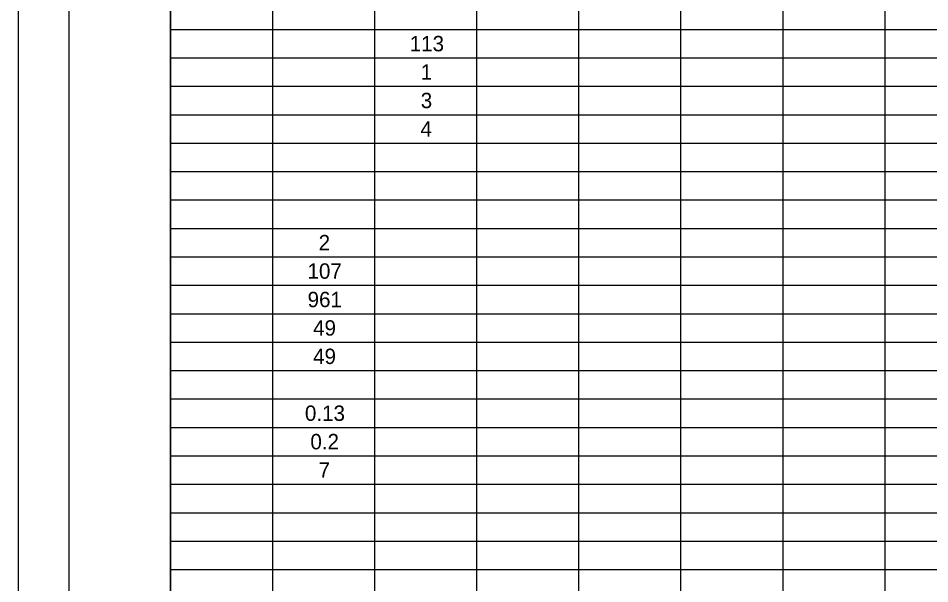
# Model space of a CAD drawing. Extents: x 0 to 34, y 0 to 22.
# Drawn here: x 0 to 8.98, y 11 to 16.57 of the extents above; entities that cross this region are included whole.
import ezdxf

# ---------------------------------------------------------------- set-up
doc = ezdxf.new("R2010")
doc.units = 0
for name, color, linetype in [('Default', 7, 'Continuous'), ('SH_Border', 7, 'Continuous'), ('SH_Cut_Line', 7, 'Continuous')]:
    doc.layers.add(name, color=color, linetype=linetype)

msp = doc.modelspace()

# ---------------------------------------------------------------- linework, layer by layer
at = {"layer": 'Default'}
for p, q in [((1.5, 21.5), (1.5, 0.5)), ((2.5046, 20.94), (2.5046, 0.5)), ((3.5092, 20.94), (3.5092, 0.5)), ((4.5138, 20.94), (4.5138, 0.5)), ((5.5184, 20.94), (5.5184, 0.5)), ((6.5229, 20.94), (6.5229, 0.5)), ((7.5275, 20.94), (7.5275, 0.5)), ((8.5321, 20.94), (8.5321, 0.5)), ((1.5, 16.46), (32, 16.46)), ((1.5, 16.18), (32, 16.18)), ((1.5, 15.9), (32, 15.9)), ((1.5, 15.62), (32, 15.62)), ((1.5, 15.34), (32, 15.34)), ((1.5, 15.06), (32, 15.06)), ((1.5, 14.78), (32, 14.78)), ((1.5, 14.5), (32, 14.5)), ((1.5, 14.22), (32, 14.22)), ((1.5, 13.94), (32, 13.94)), ((1.5, 13.66), (32, 13.66)), ((1.5, 13.38), (32, 13.38)), ((1.5, 13.1), (32, 13.1)), ((1.5, 12.82), (32, 12.82)), ((1.5, 12.54), (32, 12.54)), ((1.5, 12.26), (32, 12.26)), ((1.5, 11.98), (32, 11.98)), ((1.5, 11.7), (32, 11.7)), ((1.5, 11.42), (32, 11.42)), ((1.5, 11.14), (32, 11.14))]:
    msp.add_line(p, q, dxfattribs=at)
at = {"layer": 'SH_Border'}
for points in [[(0.5, 21.5), (1.5, 21.5), (1.5, 0.5), (0.5, 0.5)], [(1.5, 21.5), (33.5, 21.5), (33.5, 0.5), (1.5, 0.5)]]:
    msp.add_lwpolyline(points, close=True, dxfattribs=at)
at = {"layer": 'SH_Cut_Line'}
msp.add_lwpolyline([(0, 0), (34, 0), (34, 22), (0, 22)], close=True, dxfattribs=at)

# ---------------------------------------------------------------- texts
at = {"layer": 'Default'}
for s, height, p in [('113', 0.15153, (3.8548, 16.2442)), ('1', 0.1515, (3.9629, 15.9642)), ('3', 0.1515, (3.9636, 15.6842)), ('4', 0.1515, (3.9601, 15.4042)), ('2', 0.1515, (2.9584, 14.2842)), ('107', 0.15153, (2.8486, 14.0042)), ('961', 0.15153, (2.8495, 13.7242)), ('49', 0.15153, (2.9035, 13.4442)), ('49', 0.15153, (2.9035, 13.1642)), ('0.13', 0.15153, (2.823, 12.6042)), ('0.2', 0.15153, (2.8769, 12.3242)), ('7', 0.1515, (2.9574, 12.0442))]:
    msp.add_text(s, height=height, dxfattribs=at).set_placement(p)

doc.saveas('drawing.dxf')
